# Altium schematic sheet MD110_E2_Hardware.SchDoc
size 431 x 279 mm; Date: Not shown in title block; ApprovedBy: Not shown in title block; CheckedBy: Not shown in title block; Author: Not shown in title block; CompanyName: Not shown in title block; Engineer: Not shown in title block; Organization: Not shown in title block; Address1: Not shown in title block; Address2: Not shown in title block; Address3: Not shown in title block; Address4: Not shown in title block; DocumentNumber: 2; Revision: Use project parameter SCH_Rev; SheetNumber: 2; SheetTotal: 2; PageSetup: Record=PageOptions¦CenterHorizontal=True¦CenterVertical=True¦PrintScale=1.00¦XCorrection=1.00¦YCorrection=1.00¦PrintKind=0¦BorderSize=5000000¦LeftOffset=0¦BottomOffset=0¦Orientation=2¦PaperLength=1000¦PaperWidth=1000¦Scale=100¦PaperSource=15¦PrintQuality=600¦MediaType=1¦DitherType=10¦PaperKind=Letter¦PrintScaleMode=1
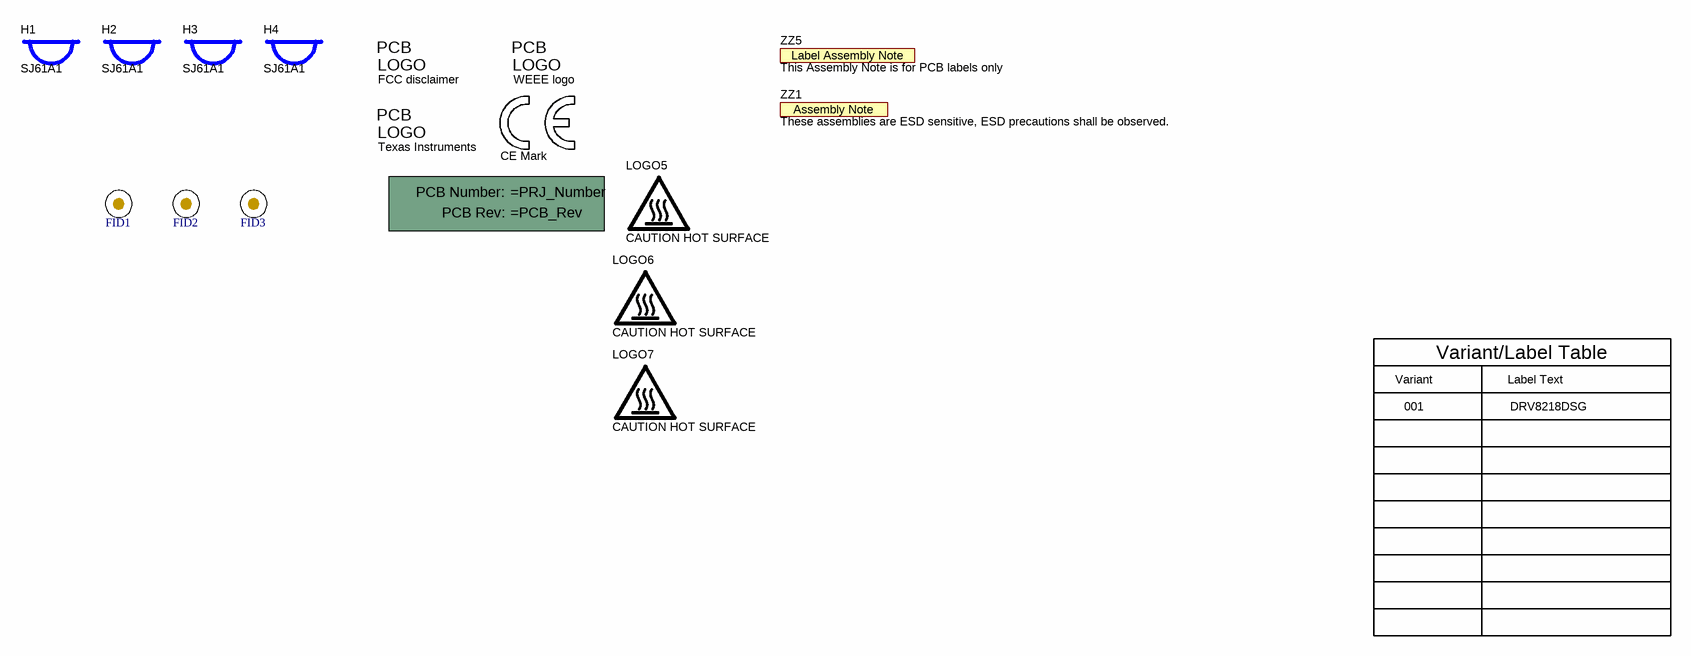
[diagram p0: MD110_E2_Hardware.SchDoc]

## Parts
!PCB1  Printed Circuit Board  (value not drawn)  (mechanical)
FID1  Fiducial  [Fiducial10-20]  (value not drawn)
FID2  Fiducial  [Fiducial10-20]  (value not drawn)
FID3  Fiducial  [Fiducial10-20]  (value not drawn)
H1  SJ61A1  [Bumpon_SJ61A1]
H2  SJ61A1  [Bumpon_SJ61A1]
H3  SJ61A1  [Bumpon_SJ61A1]
H4  SJ61A1  [Bumpon_SJ61A1]
Logo1  FCC disclaimer  [FCC_disclaimer]  (no BOM)
Logo2  Texas Instruments  [TI_Symbol_Overlay_Small]  (no BOM)
Logo3  WEEE logo  [WEEE_Minimum]  (no BOM)
Logo4  CE Mark  [CE_Mark_5mm]  (no BOM)
LOGO5  CAUTION HOT SURFACE  [IEC_HotSurface_Small]  (no BOM)
LOGO6  CAUTION HOT SURFACE  [IEC_HotSurface_Small]  (no BOM)
LOGO7  CAUTION HOT SURFACE  [IEC_HotSurface_Small]  (no BOM)
ZZ1  These assemblies are ESD sensitive, ESD precautions shall be observed.  [AssemblyNote]  (no BOM)
ZZ5  This Assembly Note is for PCB labels only  [AssemblyNoteLabel]  (no BOM)

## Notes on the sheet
- Variant/Label Table
- Variant
- 001
- Label Text
- DRV8218DSG

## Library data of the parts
!PCB1 = CMP-0003618-2: Manufacturer: Any
FID1-FID3 = CMP-0077181-1: Fiducial mark.  There is nothing to buy or mount.
H1-H4 = CMP-0003621-1: Bumpon, Cylindrical, 0.312 X 0.200, Black; Manufacturer: 3M
Logo1 = CMP-0074847-1: FCC_disclaimer
Logo2 = CMP-0074838-1: Texas Instrument Corporate Signature; SymbolCreator: a0412235; Lib Reference: TI_Logo
Logo3 = CMP-0074769-4: Manufacturer: Texas Instruments; CompType: IC; AEC Category: Q200
Logo4 = CMP-0074844-2: Manufacturer: Texas Instruments; SymbolCreator: a0412235; AEC Category: Q200; CompType: IC
LOGO5-LOGO7 = CMP-0074837-2: IEC 61010-1 Hot Surface Warning; Manufacturer: Texas Instruments; SymbolCreator: a0412235; CompType: IC; AEC Category: Q200
ZZ1 = CMP-0077236-1
ZZ5 = CMP-0003616-3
